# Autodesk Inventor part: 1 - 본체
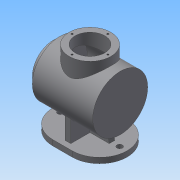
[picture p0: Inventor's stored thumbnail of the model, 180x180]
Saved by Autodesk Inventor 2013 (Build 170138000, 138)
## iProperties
Created: 2016-04
Part Number: 1 - 본체
Material: 일반
Document SubType Name: Modeling
Designer: Administrator
Density: 1 g/cm^3
Author: Administrator
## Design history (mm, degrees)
sketch "스케치1"
  geometry: L1 (-17.5, 50)-(17.5, 50); L2 (17.5, -50)-(-17.5, -50); A1 r 50 centre (17.5, 0) between (17.5, -50) and (17.5, 50); A2 r 50 centre (-17.5, 0) between (-17.5, 50) and (-17.5, -50); 2 further points
  constraints: 4 end point, 4 point on circle, 4 tangent, 2 centre point, 2 horizontal alignment, 1 horizontal, 1 midpoint, 1 parallel, 1 vertical alignment
  dimensions: "d0" = 100 distance between parallel lines of L2 L1; "d2" = 135 dimension on A2 A1
extrude "돌출1" new body sketch "스케치1" distance "d3" = 10; taper "d4" = 0 deg
sketch "스케치2"
  geometry: C1 r 50 at (0, 79); 1 further point
  constraints: 1 centre point, 1 vertical alignment
  dimensions: "d5" = 79 distance of point (0, 0) C1.centre; "d6" = 100 diameter of C1
extrude "돌출2" join sketch "스케치2" stored distance "d7" = 110; taper "d8" = 0 deg
sketch "스케치3"
  geometry: L1 (-17.5, 10)-(-67.5, 10) reference; L2 (67.5, 10)-(17.5, 10) reference; L3 (55, 29)-(-55, 29) reference; L4 (-40, 10)-(-36.65, 29); L5 (36.65, 29)-(40, 10); L6 (-36.65, 29)-(36.65, 29); L7 (-40, 10)-(40, 10); 1 further point
  constraints: 8 end point, 4 point on line, 2 collinear
  dimensions: "d9" = 40 horizontal distance of point (0, 0) L4.start; "d10" = 40 horizontal distance of point (0, 0) L5.end; "d11" = 100 deg angle of L5 L2; "d12" = 100 deg angle of L1 L4
extrude "돌출3" join sketch "스케치3" stored distance "d13" = 10; taper "d14" = 0 deg
sketch "스케치4"
  geometry: L1 (50, 10)-(-50, 10) reference; L2 (-40, 49)-(-40, 10); L3 (40, 49)-(40, 10); A1 r 50 centre (0, 79) between (-40, 49) and (40, 49) reference; 1 further point
  constraints: 4 end point, 2 point on circle, 2 point on line, 1 perpendicular, 1 vertical
  dimensions: "d15" = 40 distance from line of L3 point (0, 0); "d16" = 40 horizontal distance of point (0, 0) L2.end
extrude "돌출4" join sketch "스케치4" stored distance "d17" = 10; taper "d18" = 0 deg
sketch "스케치5"
  geometry: C1 r 50 at (0, 0) reference; C2 r 38 at (0, 0); 1 further point
  constraints: 1 centre point, 1 coincident
  dimensions: "d19" = 76 diameter of C2
extrude "돌출5" join sketch "스케치5" distance "d21" = 12; taper "d22" = 0 deg
node "작업 평면1"
sketch "스케치6"
  geometry: C1 r 38 at (0, 0); 1 further point
  constraints: 1 centre point, 1 coincident
  dimensions: "d24" = 76 diameter of C1
extrude "돌출6" join sketch "스케치6" distance "d26" = 40; taper "d27" = 0 deg
sketch "스케치9"
  geometry: L1 (-55, 129)-(-55, 29) reference; L2 (67, 41)-(67, 117) reference; L3 (-55, 79)-(67, 79); L4 (-52, 79)-(-52, 126); L5 (-52, 126)-(52, 126); L6 (52, 126)-(52, 106); L7 (52, 106)-(67, 106); L8 (55, 129)-(-55, 129) reference; L9 (55, 29)-(55, 129) reference; 1 further point
  constraints: 10 end point, 3 perpendicular, 2 midpoint, 2 point on line, 1 parallel
  dimensions: "d28" = 3 distance between parallel lines of L1 L4; "d29" = 3 distance between parallel lines of L8 L5; "d30" = 54 diameter of L7 L3; "d31" = 3 distance between parallel lines of L9 L6
revolve "회전1" sketch "스케치9" stored, may be unused: angle "d32" = 90 deg
hole "구멍1" diameter "d35" = 54; stored, may be unused: countersink angle "d39" = 90 deg, drill point angle "d41" = 0 deg; dims "d33" = 10, "d34" = 10, "d36" = 6, "d37" = 4, "d38" = 2, "d40" = 30
sketch "스케치10"
  geometry: 3 further points
  constraints: 2 horizontal alignment
  dimensions: "d42" = 54 distance of point (0, 0) point (-54, 0); "d43" = 54 distance of point (54, 0) point (0, 0)
hole "구멍2" sketch "스케치10" at (-54, 0), (54, 0) diameter "d44" = 10; stored, may be unused: countersink angle "d48" = 90 deg, drill point angle "d50" = 0 deg; dims "d45" = 6, "d46" = 4, "d47" = 2, "d49" = 10
sketch "스케치11"
  geometry: C1 r 47 at (0, 0) reference; C2 r 27 at (0, 0) reference; A1 r 32.5 centre (0, 0) between (32.5, 0) and (0, 32.5); 3 further points
  constraints: 4 point on circle, 1 centre point, 1 coincident
  dimensions: "d51" = 65 diameter of A1
hole "구멍3" sketch "스케치11" at (32.5, 0), (0, 32.5), (-32.5, 0), (0, -32.5) diameter "d54" = 3.242; stored, may be unused: countersink angle "d58" = 90 deg, drill point angle "d60" = 118 deg; dims "d55" = 8, "d56" = 4, "d57" = 2, "d59" = 10
sketch "스케치12"
  geometry: A1 r 32.5 centre (0, 0) between (0, 32.5) and (32.5, 0); 3 further points
  constraints: 4 point on circle, 2 horizontal alignment, 2 vertical alignment, 1 centre point, 1 coincident
  dimensions: "d61" = 65 diameter of A1
hole "구멍4" sketch "스케치12" at (0, 32.5), (32.5, 0), (0, -32.5), (-32.5, 0) diameter "d63" = 3.242; stored, may be unused: countersink angle "d67" = 90 deg, drill point angle "d69" = 118 deg; dims "d64" = 8, "d65" = 4, "d66" = 2, "d68" = 10
node "솔리드1"
node "투영된 루프1"
node "투영된 루프3"
other parameters: "d23" = 144
